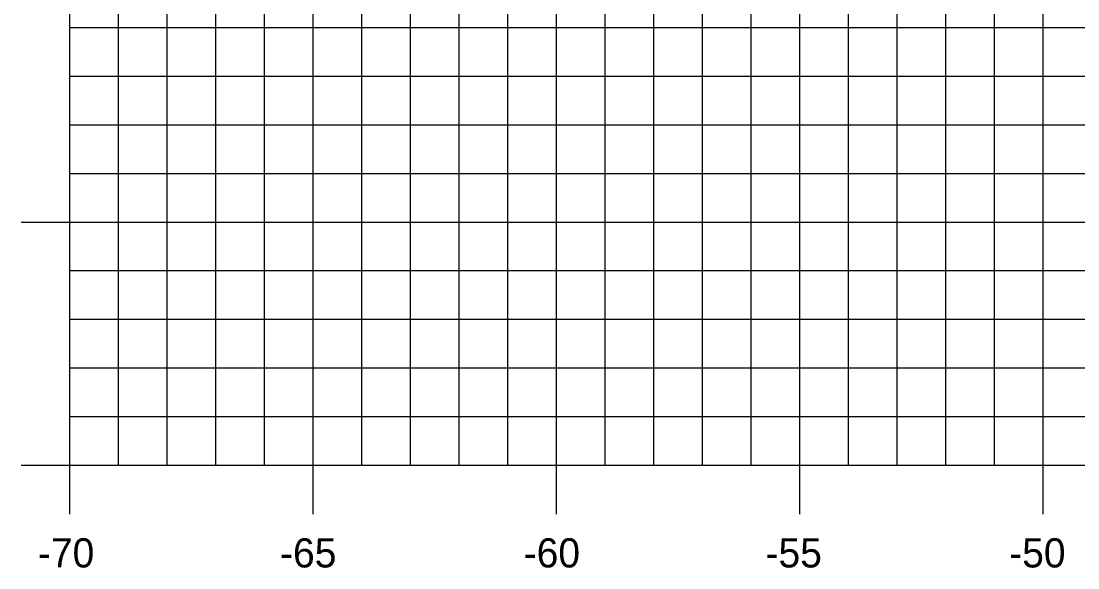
# Model space of a CAD drawing. Extents: x 1147633 to 1147803, y 608981 to 609091.
# Drawn here: x 1147645.45 to 1147667.17, y 609048.23 to 609059.46 of the extents above; entities that cross this region are included whole.
import ezdxf

# ---------------------------------------------------------------- set-up
doc = ezdxf.new("R2010")
doc.units = 0
for name, color, linetype in [('H_V ANNOTATION', 7, 'Continuous'), ('MAJOR', 7, 'Continuous'), ('MINOR', 7, 'Continuous')]:
    doc.layers.add(name, color=color, linetype=linetype)

msp = doc.modelspace()

# ---------------------------------------------------------------- linework, layer by layer
at = {"layer": 'MAJOR'}
for p, q in [((1147646.454, 609050.335), (1147646.454, 609070.335)), ((1147646.454, 609050.335), (1147646.454, 609070.335)), ((1147651.454, 609050.335), (1147651.454, 609070.335)), ((1147656.454, 609050.335), (1147656.454, 609070.335)), ((1147661.454, 609050.335), (1147661.454, 609070.335)), ((1147666.454, 609050.335), (1147666.454, 609070.335)), ((1147645.452, 609055.335), (1147646.454, 609055.335)), ((1147646.454, 609055.335), (1147786.454, 609055.335)), ((1147645.452, 609050.335), (1147646.454, 609050.335)), ((1147646.454, 609050.335), (1147786.454, 609050.335)), ((1147646.454, 609050.335), (1147786.454, 609050.335)), ((1147646.454, 609049.333), (1147646.454, 609050.335)), ((1147651.454, 609049.333), (1147651.454, 609050.335)), ((1147656.454, 609049.333), (1147656.454, 609050.335)), ((1147661.454, 609049.333), (1147661.454, 609050.335)), ((1147666.454, 609049.333), (1147666.454, 609050.335))]:
    msp.add_line(p, q, dxfattribs=at)
at = {"layer": 'MINOR'}
for p, q in [((1147647.454, 609050.335), (1147647.454, 609070.335)), ((1147648.454, 609050.335), (1147648.454, 609070.335)), ((1147649.454, 609050.335), (1147649.454, 609070.335)), ((1147650.454, 609050.335), (1147650.454, 609070.335)), ((1147652.454, 609050.335), (1147652.454, 609070.335)), ((1147653.454, 609050.335), (1147653.454, 609070.335)), ((1147654.454, 609050.335), (1147654.454, 609070.335)), ((1147655.454, 609050.335), (1147655.454, 609070.335)), ((1147657.454, 609050.335), (1147657.454, 609070.335)), ((1147658.454, 609050.335), (1147658.454, 609070.335)), ((1147659.454, 609050.335), (1147659.454, 609070.335)), ((1147660.454, 609050.335), (1147660.454, 609070.335)), ((1147662.454, 609050.335), (1147662.454, 609070.335)), ((1147663.454, 609050.335), (1147663.454, 609070.335)), ((1147664.454, 609050.335), (1147664.454, 609070.335)), ((1147665.454, 609050.335), (1147665.454, 609070.335)), ((1147646.454, 609059.335), (1147786.454, 609059.335)), ((1147646.454, 609059.335), (1147647.456, 609059.335)), ((1147646.454, 609058.335), (1147786.454, 609058.335)), ((1147646.454, 609058.335), (1147647.456, 609058.335)), ((1147646.454, 609057.335), (1147786.454, 609057.335)), ((1147646.454, 609057.335), (1147647.456, 609057.335)), ((1147646.454, 609056.335), (1147786.454, 609056.335)), ((1147646.454, 609056.335), (1147647.456, 609056.335)), ((1147646.454, 609054.335), (1147786.454, 609054.335)), ((1147646.454, 609054.335), (1147647.456, 609054.335)), ((1147646.454, 609053.335), (1147786.454, 609053.335)), ((1147646.454, 609053.335), (1147647.456, 609053.335)), ((1147646.454, 609052.335), (1147786.454, 609052.335)), ((1147646.454, 609052.335), (1147647.456, 609052.335)), ((1147646.454, 609051.335), (1147786.454, 609051.335)), ((1147646.454, 609051.335), (1147647.456, 609051.335))]:
    msp.add_line(p, q, dxfattribs=at)

# ---------------------------------------------------------------- texts
at = {"layer": 'H_V ANNOTATION'}
for s, p in [('-70', (1147645.796, 609048.235)), ('-65', (1147650.772, 609048.235)), ('-60', (1147655.78, 609048.235)), ('-55', (1147660.75, 609048.235)), ('-50', (1147665.758, 609048.235))]:
    msp.add_text(s, height=0.6, dxfattribs=at).set_placement(p)
at = {"layer": 'MAJOR'}
msp.add_text('-', height=0.006, dxfattribs=at).set_placement((1147646.45, 609050.335))

doc.saveas('drawing.dxf')
